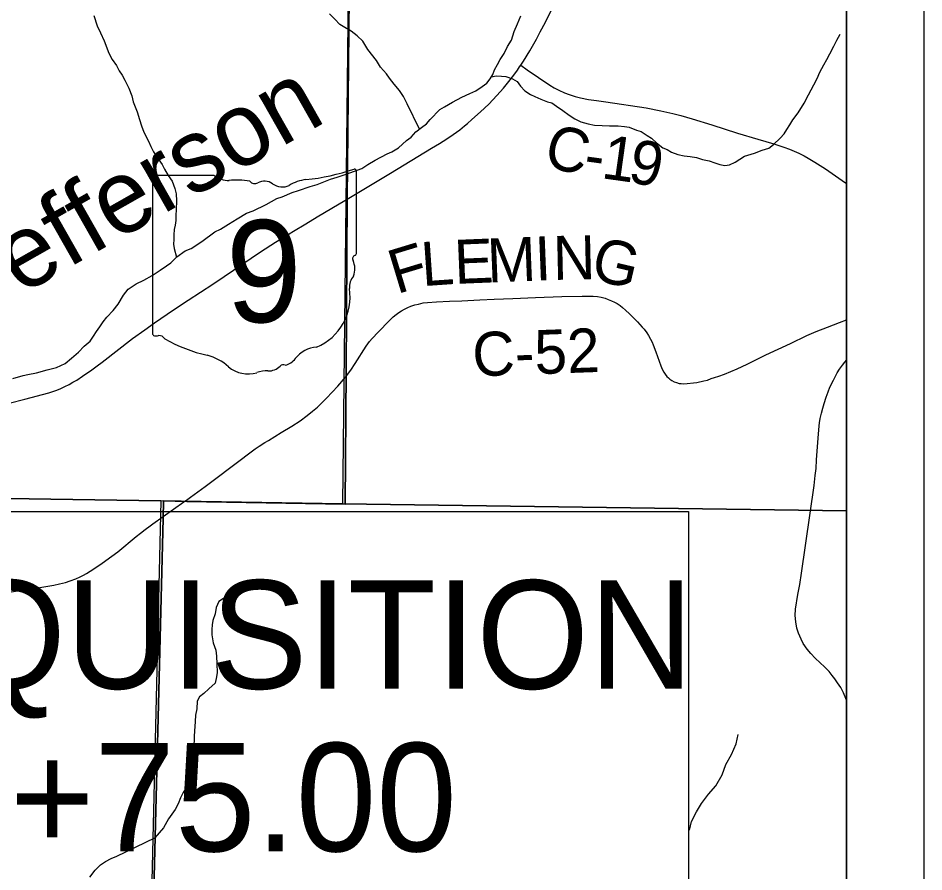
# Model space of a CAD drawing. Extents: x 0 to 34, y 0 to 22.
# Drawn here: x 16.329 to 17.5, y 18.414 to 19.517 of the extents above; entities that cross this region are included whole.
import ezdxf

# ---------------------------------------------------------------- set-up
doc = ezdxf.new("R2010")
doc.units = 0
for name, color, linetype in [('GM_X_Corporation', 7, 'Continuous'), ('GM_X_County_Road', 7, 'Continuous'), ('GM_X_County_Road_Text', 7, 'Continuous'), ('GM_X_Minor_River', 7, 'Continuous'), ('GM_X_Minor_River_Text', 7, 'Continuous'), ('GM_X_State_Location', 7, 'Continuous'), ('GM_X_State_Route', 7, 'Continuous'), ('GM_X_State_Shield', 7, 'Continuous'), ('SH_Data', 7, 'Continuous'), ('SH_Text', 7, 'Continuous')]:
    doc.layers.add(name, color=color, linetype=linetype)

msp = doc.modelspace()

# ---------------------------------------------------------------- linework, layer by layer
at = {"layer": 'GM_X_Corporation'}
msp.add_lwpolyline([(13.2742, 17.4966), (14.0954, 17.4811), (14.726, 17.4654), (14.7561, 17.4645), (15.8426, 17.4278), (15.8844, 17.4269), (16.4807, 17.4161), (16.4886, 17.7392), (16.5168, 18.8707), (16.5174, 18.8935), (16.5475, 18.8929), (16.752, 18.8891), (16.7532, 19.0614), (16.7547, 19.2837), (16.7652, 20.328), (16.7661, 20.4), (11.5001, 20.4)], dxfattribs=at)
for points in [[(17.4, 16.913), (17.4, 20.4), (16.7661, 20.4), (16.7652, 20.328), (16.7547, 19.2837), (16.7532, 19.0614), (16.752, 18.8891), (16.5475, 18.8929), (16.5174, 18.8935), (16.5168, 18.8707), (16.4886, 17.7392), (16.4807, 17.4161), (16.4704, 17.0104), (16.4703, 17.0036), (16.4689, 16.9245), (16.5516, 16.9243)], [(16.7598, 19.9006), (16.7485, 18.8896), (16.5138, 18.8938), (15.5197, 18.9088), (15.5496, 19.9206)], [(17.4, 18.8808), (17.4, 19.8932), (16.7598, 19.9006), (16.7485, 18.8896)], [(15.5197, 18.9088), (16.5138, 18.8938), (16.4906, 17.9114), (15.5004, 17.9447)], [(17.4, 17.9189), (17.4, 18.8808), (16.7485, 18.8896), (16.5138, 18.8938), (16.4906, 17.9114)]]:
    msp.add_lwpolyline(points, close=True, dxfattribs=at)
at = {"layer": 'GM_X_County_Road'}
for points in [[(16.979, 19.4562), (16.9875, 19.4504), (17.0166, 19.4304), (17.0223, 19.4271), (17.0283, 19.4239), (17.0355, 19.4207), (17.0417, 19.4183), (17.0493, 19.4159), (17.0562, 19.4141), (17.0665, 19.4121), (17.077, 19.4105), (17.0891, 19.4087), (17.1411, 19.4012), (17.1602, 19.3975), (17.1755, 19.394), (17.1861, 19.3911), (17.2006, 19.3869), (17.2261, 19.379), (17.2593, 19.3684), (17.2855, 19.3608), (17.3062, 19.3545), (17.3192, 19.3504), (17.3263, 19.3478), (17.3323, 19.3454), (17.3386, 19.3424), (17.3452, 19.3391), (17.3504, 19.3361), (17.3589, 19.3311), (17.3727, 19.3223), (17.3815, 19.3165), (17.3901, 19.3105), (17.3988, 19.3044), (17.4, 19.3036)], [(16.7525, 19.0535), (16.7593, 19.0622), (16.7652, 19.071), (16.7794, 19.0935), (16.7836, 19.0992), (16.7869, 19.1031), (16.7947, 19.1114), (16.8096, 19.1266), (16.8143, 19.1312), (16.8181, 19.1344), (16.8214, 19.1369), (16.8249, 19.139), (16.8288, 19.1411), (16.833, 19.1431), (16.8369, 19.1448), (16.842, 19.1466), (16.8467, 19.1478), (16.853, 19.1492), (16.8585, 19.1499), (16.87, 19.1507), (16.8869, 19.1514), (16.9027, 19.152), (16.9261, 19.1531), (16.9446, 19.1542), (16.9687, 19.1547), (16.998, 19.1561), (17.032, 19.1574), (17.0582, 19.158), (17.0645, 19.1581), (17.0728, 19.1579), (17.078, 19.1575), (17.083, 19.1567), (17.0883, 19.1553), (17.0922, 19.1537), (17.0964, 19.1519), (17.1001, 19.1502), (17.1036, 19.1484), (17.1073, 19.1459), (17.1104, 19.1433), (17.1142, 19.1398), (17.1195, 19.135), (17.125, 19.1295), (17.1297, 19.1246), (17.136, 19.1178), (17.1383, 19.1152), (17.1418, 19.1105), (17.1443, 19.1071), (17.1468, 19.1023), (17.1489, 19.0983), (17.1503, 19.0949), (17.1536, 19.0861), (17.16, 19.0678), (17.1618, 19.0638), (17.1639, 19.0597), (17.1657, 19.0571), (17.1679, 19.0543), (17.1699, 19.0523), (17.1718, 19.0506), (17.1741, 19.049), (17.1774, 19.0474), (17.1804, 19.0463), (17.1837, 19.0453), (17.1865, 19.045), (17.1896, 19.0449), (17.2067, 19.0463), (17.2158, 19.0484), (17.2203, 19.0496), (17.2252, 19.0514), (17.2296, 19.0529), (17.2349, 19.0547), (17.2423, 19.0573), (17.2588, 19.0641), (17.2717, 19.0703), (17.2957, 19.0821), (17.3275, 19.0969), (17.3489, 19.1072), (17.3608, 19.1122), (17.3754, 19.1179), (17.3909, 19.1238), (17.4, 19.1274)], [(17.4, 18.636), (17.396, 18.6458), (17.3925, 18.6526), (17.3885, 18.6585), (17.3849, 18.6636), (17.3816, 18.6679), (17.3774, 18.6731), (17.3716, 18.6792), (17.3659, 18.6844), (17.3593, 18.6905), (17.3539, 18.6962), (17.3492, 18.702), (17.3441, 18.7095), (17.3414, 18.7149), (17.3378, 18.7228), (17.3358, 18.7291), (17.3345, 18.7373), (17.3338, 18.7456), (17.334, 18.7538), (17.337, 18.7727), (17.3396, 18.7854), (17.3417, 18.8003), (17.3581, 18.9133), (17.3596, 18.9264), (17.3606, 18.9353), (17.3613, 18.9464), (17.3634, 18.9744), (17.3647, 18.9903), (17.3651, 18.9944), (17.3661, 18.9999), (17.3676, 19.0067), (17.3694, 19.0133), (17.3712, 19.0194), (17.3737, 19.0275), (17.3761, 19.0343), (17.3786, 19.0404), (17.383, 19.0493), (17.3881, 19.0588), (17.3911, 19.0637), (17.3948, 19.0689), (17.3979, 19.0728), (17.4, 19.0751)], [(16.5521, 18.8984), (16.5712, 18.9121), (16.5816, 18.9199), (16.6358, 18.9608), (16.6408, 18.9642), (16.6481, 18.9688), (16.6529, 18.9716), (16.6694, 18.9818), (16.6833, 18.99), (16.694, 18.9969), (16.7031, 19.004), (16.7099, 19.0093), (16.7162, 19.0147), (16.7221, 19.0202), (16.728, 19.0261), (16.7427, 19.0417), (16.7525, 19.0535)], [(16.4936, 18.8565), (16.4999, 18.8611), (16.5034, 18.8637), (16.5438, 18.8925), (16.5486, 18.8959), (16.5521, 18.8984)], [(16.3118, 18.7746), (16.355, 18.7814), (16.3758, 18.7848), (16.3828, 18.7862), (16.3905, 18.7881), (16.3967, 18.7901), (16.4041, 18.7929), (16.4098, 18.7956), (16.4141, 18.7977), (16.4178, 18.7998), (16.4227, 18.8028), (16.4364, 18.8119), (16.4429, 18.8164), (16.4581, 18.8277), (16.482, 18.8474), (16.4875, 18.8518), (16.4936, 18.8565)]]:
    msp.add_lwpolyline(points, dxfattribs=at)
at = {"layer": 'GM_X_Minor_River'}
for points in [[(16.4275, 19.5202), (16.4316, 19.5069), (16.4358, 19.4982), (16.4406, 19.4875), (16.4466, 19.4719), (16.4512, 19.4635), (16.4564, 19.4559), (16.4602, 19.4491), (16.464, 19.4434), (16.4674, 19.4369), (16.4726, 19.4266), (16.4764, 19.4167), (16.4782, 19.4087), (16.4831, 19.3962), (16.4865, 19.3859), (16.4887, 19.3779), (16.4917, 19.3699), (16.4981, 19.3581), (16.5008, 19.3513), (16.5045, 19.3444), (16.5106, 19.3353), (16.5155, 19.328), (16.5185, 19.3219), (16.5234, 19.3136), (16.5286, 19.3063), (16.532, 19.2968), (16.5339, 19.29), (16.5342, 19.2812), (16.5338, 19.2698), (16.5334, 19.2622), (16.5334, 19.2558), (16.5322, 19.2497), (16.531, 19.244), (16.5306, 19.2372), (16.5306, 19.2311), (16.5302, 19.225), (16.5309, 19.2193), (16.5342, 19.2082)], [(16.8482, 19.3738), (16.8323, 19.4063), (16.8274, 19.4158), (16.8225, 19.4234), (16.8153, 19.4318), (16.8093, 19.4394), (16.8055, 19.4452), (16.7979, 19.4535), (16.7927, 19.4623), (16.7813, 19.4764), (16.7749, 19.4871), (16.7678, 19.4943), (16.7598, 19.5), (16.7515, 19.505), (16.7451, 19.5088), (16.7386, 19.5157), (16.7318, 19.5226)], [(16.9352, 19.4329), (16.9394, 19.4386), (16.9428, 19.4443), (16.9451, 19.4503), (16.949, 19.4572), (16.9524, 19.4636), (16.9574, 19.4712), (16.962, 19.4803), (16.9669, 19.4886), (16.9704, 19.4996), (16.975, 19.5095), (16.9792, 19.5201)], [(16.941, 19.4412), (16.9474, 19.4424), (16.9542, 19.4419), (16.9599, 19.4415), (16.9682, 19.4385), (16.9743, 19.435), (16.9788, 19.4293), (16.9845, 19.4232), (16.9917, 19.4183), (16.9974, 19.4156), (17.0049, 19.4125), (17.0136, 19.4091), (17.0193, 19.4075), (17.0254, 19.4033), (17.0333, 19.3976), (17.0417, 19.3919), (17.0488, 19.3869), (17.0568, 19.3831), (17.0663, 19.3804), (17.0742, 19.3788), (17.0841, 19.3784), (17.0936, 19.378), (17.105, 19.3779), (17.1133, 19.3771), (17.119, 19.3764), (17.1285, 19.3725), (17.1345, 19.3706), (17.1425, 19.3653), (17.1481, 19.3618), (17.1546, 19.3561), (17.1625, 19.3496), (17.1682, 19.3473), (17.1739, 19.3439), (17.1822, 19.3408), (17.1902, 19.3392), (17.1978, 19.3385), (17.2061, 19.3369), (17.2141, 19.3346), (17.2224, 19.3327), (17.23, 19.33), (17.2364, 19.328), (17.2429, 19.3265), (17.2486, 19.3276), (17.2562, 19.331), (17.2622, 19.3348), (17.2683, 19.3386), (17.2809, 19.3427), (17.2908, 19.3465), (17.2995, 19.3491), (17.3056, 19.3536), (17.3143, 19.362), (17.3193, 19.3676), (17.3227, 19.3733), (17.3269, 19.379), (17.3308, 19.3858), (17.3376, 19.3949), (17.3453, 19.407), (17.351, 19.418), (17.3579, 19.4309), (17.3621, 19.4389), (17.3656, 19.4473), (17.3705, 19.4567), (17.3744, 19.4636), (17.3786, 19.4711), (17.3835, 19.4806), (17.3874, 19.4886), (17.392, 19.4962)], [(16.3226, 19.0517), (16.3359, 19.0555), (16.342, 19.0566), (16.3534, 19.0588), (16.3671, 19.0626), (16.3792, 19.066), (16.3903, 19.0709), (16.3983, 19.0777), (16.4074, 19.0856), (16.415, 19.0932), (16.4226, 19.0996), (16.4268, 19.1061), (16.4307, 19.1121), (16.4352, 19.1182), (16.4394, 19.1246), (16.444, 19.1307), (16.4524, 19.1394), (16.4589, 19.1474), (16.4658, 19.1591), (16.4715, 19.1671), (16.4822, 19.1739), (16.4917, 19.1784), (16.5027, 19.1844), (16.513, 19.1916), (16.521, 19.1973), (16.5267, 19.2011), (16.5347, 19.2087), (16.5453, 19.2166), (16.5529, 19.2196), (16.567, 19.2287), (16.5838, 19.2408), (16.591, 19.2445), (16.6013, 19.251), (16.6127, 19.2578), (16.6248, 19.2653), (16.6332, 19.2683), (16.6499, 19.2763), (16.664, 19.2842), (16.6705, 19.2864), (16.6838, 19.2917), (16.6918, 19.2943), (16.707, 19.2996), (16.7157, 19.3022), (16.7332, 19.309), (16.7419, 19.3116), (16.7545, 19.3161), (16.7674, 19.3207), (16.7735, 19.3229), (16.7815, 19.3278), (16.791, 19.3335), (16.8062, 19.3418), (16.8123, 19.3444), (16.821, 19.3497), (16.8313, 19.3588), (16.8374, 19.3633), (16.8435, 19.3702), (16.8507, 19.3758), (16.8572, 19.3804), (16.8618, 19.3861), (16.8743, 19.3989), (16.8804, 19.4023), (16.8907, 19.4084), (16.9029, 19.4148), (16.9131, 19.4197), (16.9211, 19.4231), (16.9291, 19.4287), (16.9352, 19.4329)], [(16.6224, 18.7809), (16.6113, 18.7756), (16.6033, 18.7695), (16.595, 18.7673), (16.5889, 18.7635), (16.5855, 18.7559), (16.5839, 18.7476), (16.5812, 18.7392), (16.5804, 18.7335), (16.5796, 18.7274), (16.5796, 18.7206), (16.5815, 18.71), (16.5848, 18.7008), (16.5859, 18.6928), (16.5863, 18.683), (16.5866, 18.6719), (16.5858, 18.6662), (16.5839, 18.6583), (16.5759, 18.6507), (16.5694, 18.6446), (16.5637, 18.6405), (16.561, 18.6348), (16.5602, 18.6249), (16.5587, 18.6169), (16.5583, 18.6086), (16.5574, 18.596), (16.557, 18.5896), (16.557, 18.5831), (16.5551, 18.5725), (16.5543, 18.5634), (16.5542, 18.5569), (16.5538, 18.5508), (16.5523, 18.5436), (16.5511, 18.536), (16.5484, 18.5292), (16.5465, 18.5231), (16.5427, 18.5167), (16.5392, 18.5099), (16.5362, 18.5023), (16.5323, 18.4951), (16.5281, 18.489), (16.5236, 18.4829), (16.5174, 18.4712), (16.5062, 18.4582)], [(17.1973, 18.4683), (17.1996, 18.4796), (17.2061, 18.4918), (17.2125, 18.5028), (17.2217, 18.5149), (17.2312, 18.5255), (17.2395, 18.5396), (17.2441, 18.5532), (17.2513, 18.5661), (17.2574, 18.5798), (17.2601, 18.5919)], [(16.422, 18.4076), (16.4291, 18.4165), (16.4358, 18.4234), (16.4422, 18.4277), (16.4497, 18.4316), (16.4572, 18.4348), (16.5062, 18.4582)]]:
    msp.add_lwpolyline(points, dxfattribs=at)
at = {"layer": 'GM_X_State_Route'}
for points in [[(16.7547, 19.2833), (16.8105, 19.3168), (16.8638, 19.3489), (16.8741, 19.3552), (16.8837, 19.3612), (16.8916, 19.3667), (16.9002, 19.3729), (16.9065, 19.3779), (16.91, 19.3809), (16.9158, 19.3859), (16.9271, 19.396), (16.9376, 19.4061), (16.9483, 19.4173), (16.9566, 19.4266), (16.962, 19.4332), (16.97, 19.4435), (16.9747, 19.45), (16.9774, 19.4539), (16.979, 19.4562), (16.9824, 19.4614), (16.9909, 19.4747), (16.9993, 19.4897), (17.0043, 19.4992), (17.0109, 19.5119), (17.0236, 19.5373)], [(16.6742, 19.235), (16.6854, 19.2419), (16.7011, 19.2515), (16.7161, 19.2605), (16.7444, 19.2772), (16.7547, 19.2833)], [(16.3179, 19.0199), (16.3381, 19.025), (16.3693, 19.033), (16.3744, 19.0346), (16.3781, 19.036), (16.3838, 19.0383), (16.3899, 19.0412), (16.3952, 19.0438), (16.4003, 19.0467), (16.4052, 19.0496), (16.4125, 19.0544), (16.4247, 19.0627), (16.4318, 19.068), (16.4381, 19.0728), (16.4774, 19.1031), (16.4932, 19.1145), (16.5058, 19.1235), (16.5304, 19.1404), (16.5492, 19.1529), (16.581, 19.1736), (16.5958, 19.1835), (16.6427, 19.2152), (16.662, 19.2275), (16.6742, 19.235)]]:
    msp.add_lwpolyline(points, dxfattribs=at)
at = {"layer": 'GM_X_State_Shield'}
for p, q in [((16.7669, 19.214), (16.7669, 19.3187)), ((16.5032, 19.3103), (16.5032, 19.1102)), ((16.583, 19.3137), (16.5058, 19.3137)), ((16.7669, 19.214), (16.7669, 19.214))]:
    msp.add_line(p, q, dxfattribs=at)
for centre, radius, start, end in [((16.673, 19.5866), 0.2796, 275.8445, 288.9065), ((16.764, 19.3191), 0.00294, 351.8621, 97.738), ((16.5062, 19.3107), 0.00305, 98.1301, 188.1301), ((16.6014, 19.337), 0.0296, 231.6195, 271.1119), ((16.6112, 19.2014), 0.1064, 80.4867, 94.9883), ((16.6354, 19.3118), 0.00855, 219.7921, 297.1024), ((16.6479, 19.2886), 0.0178, 54.4667, 119.1411), ((16.6709, 19.3204), 0.0214, 233.8562, 294.8282), ((16.7086, 19.2526), 0.0563, 97.3462, 120.7689), ((16.7662, 19.2063), 0.00454, 107.944, 210.337), ((16.7638, 19.2136), 0.00314, 289.6038, 7.7341), ((16.7373, 19.1931), 0.0273, 340.033, 23.6496), ((16.7774, 19.1702), 0.0198, 136.8065, 186.9296), ((16.6886, 19.1569), 0.0699, 292.3089, 8.9858), ((16.5063, 19.1097), 0.00308, 171.9584, 258.3066), ((16.5067, 19.1302), 0.0235, 267.339, 280.6039), ((16.5115, 19.0986), 0.00848, 29.7484, 93.2717), ((16.6186, 19.2784), 0.2019, 240.4129, 257.1985), ((16.7181, 19.054), 0.0383, 94.4031, 142.5768), ((16.5584, 19.0203), 0.0632, 47.1842, 75.836), ((16.6722, 19.0633), 0.00601, 65.7517, 132.6484), ((16.6696, 19.0908), 0.0226, 282.8732, 323.2771), ((16.6267, 19.0976), 0.0401, 230.7004, 286.2918), ((16.6499, 19.0285), 0.0329, 85.6951, 111.2099), ((16.6528, 19.0827), 0.0214, 268.777, 315.5493)]:
    msp.add_arc(centre, radius, start, end, dxfattribs=at)
at = {"layer": 'SH_Data'}
for points in [[(10.5, 20.5), (17.5, 20.5), (17.5, 13.5), (10.5, 13.5)], [(10.6, 20.4), (17.4, 20.4), (17.4, 13.6), (10.6, 13.6)]]:
    msp.add_lwpolyline(points, close=True, dxfattribs=at)
at = {"layer": 'SH_Text'}
msp.add_lwpolyline([(15.4984, 18.8798), (17.1957, 18.8798), (17.1957, 18.1549), (15.4984, 18.1549)], close=True, dxfattribs=at)

# ---------------------------------------------------------------- texts
at = {"layer": 'GM_X_County_Road_Text'}
for s, height, rotation, p in [('C', 0.0568, 345.5103, (17.0065, 19.3268)), ('1', 0.0568, 352.023, (17.0818, 19.3105)), ('9', 0.0568, 349.4708, (17.1158, 19.3058)), ('-', 0.0568, 352.1804, (17.0588, 19.3137)), ('E', 0.0568, 2.3406, (16.894, 19.1737)), ('M', 0.0568, 2.2749, (16.9365, 19.1754)), ('I', 0.0568, 2.2722, (16.9981, 19.1779)), ('N', 0.0568, 1.2823, (17.0211, 19.1788)), ('G', 0.0568, 346.7351, (17.0674, 19.1803)), ('F', 0.0568, 16.9081, (16.8187, 19.1603)), ('L', 0.0568, 3.9501, (16.852, 19.1708)), ('C-52', 0.05682, 2.0542, (16.9174, 19.0542))]:
    msp.add_text(s, height=height, rotation=rotation, dxfattribs=at).set_placement(p)
at = {"layer": 'GM_X_Minor_River_Text'}
msp.add_text('Jefferson', height=0.0947, rotation=29.5899, dxfattribs=at).set_placement((16.2769, 19.1272))
at = {"layer": 'GM_X_State_Location'}
for s in ['s', 'r']:
    msp.add_text(s, height=0.000189, dxfattribs=at).set_placement((16.6321, 19.1969))
msp.add_text('9', height=0.000189, rotation=0, dxfattribs=at).set_placement((16.6036, 19.1832))
at = {"layer": 'GM_X_State_Shield'}
msp.add_text('9', height=0.1318, dxfattribs=at).set_placement((16.5979, 19.1243))
at = {"layer": 'SH_Text'}
for s, p in [('END ACQUISITION', (15.5382, 18.6509)), ('STA. 900+75.00', (15.5382, 18.4409))]:
    msp.add_text(s, height=0.14, dxfattribs=at).set_placement(p)

doc.saveas('drawing.dxf')
